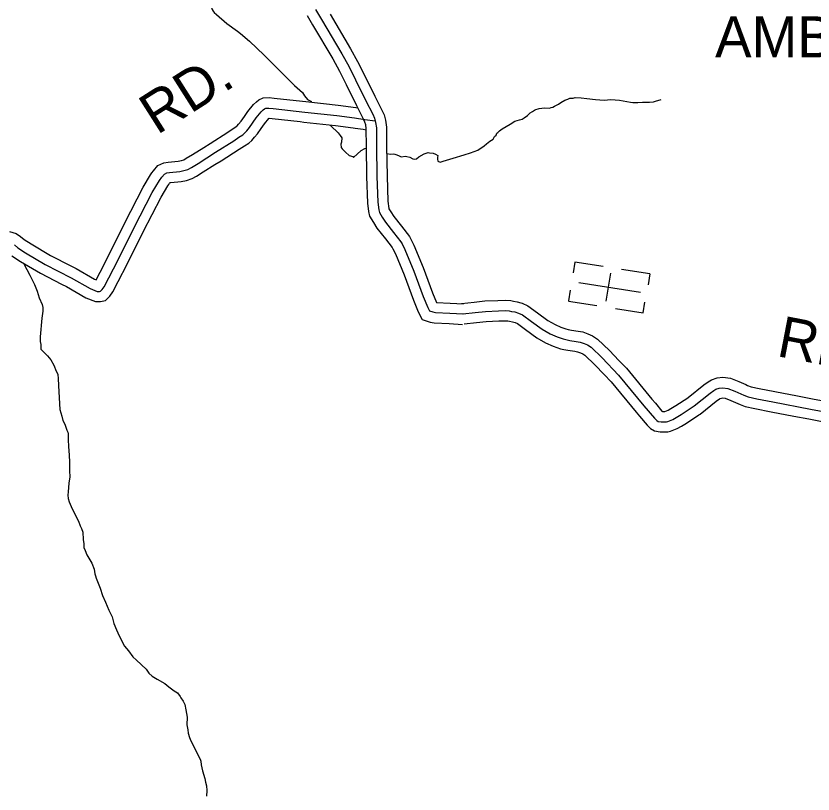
# Model space of a CAD drawing. Extents: x 1551132 to 1791609, y 378168 to 563823.
# Drawn here: x 1629673 to 1636863, y 428427 to 435445 of the extents above; entities that cross this region are included whole.
import ezdxf

# ---------------------------------------------------------------- set-up
doc = ezdxf.new("R2010")
doc.units = 0
for name, color, linetype in [('DESIGN - ROW - Right-of-Way and Easement Labels', 7, 'Continuous'), ('DESIGN - TRANSPORTATION - Text', 7, 'Continuous'), ('DESIGN - UTILITIES - Cable (Underground) with Text', 7, 'Continuous'), ('SURVEY - PROPERTY - Owners', 7, 'Continuous')]:
    doc.layers.add(name, color=color, linetype=linetype)

msp = doc.modelspace()

# ---------------------------------------------------------------- linework, layer by layer
at = {"layer": 'DESIGN - TRANSPORTATION - Text'}
for points in [[(1631371.443, 435634.795), (1631393.392, 435628.554), (1631397.376, 435626.512), (1631405.109, 435598.37), (1631428.658, 435550.027), (1631442.216, 435503.792), (1631452.066, 435487.658), (1631459.949, 435475.55), (1631481.79, 435457.283), (1631575.08, 435378.156), (1631670.469, 435309.029), (1631698.277, 435286.695), (1631779.658, 435217.71), (1631912.522, 435092.082), (1632186.032, 434816.683), (1632257.488, 434755.823), (1632277.205, 434725.556), (1632302.887, 434691.221), (1632340.178, 434672.062)], [(1633715.795, 434191.651), (1633772.186, 434210.368), (1633838.359, 434233.794), (1633896.683, 434273.311), (1633918.832, 434291.137), (1633949.048, 434316.896), (1633977.189, 434334.663), (1633989.406, 434358.58), (1634005.505, 434370.456), (1634011.647, 434386.423), (1634019.713, 434394.356), (1634035.83, 434408.232), (1634057.979, 434426.057), (1634132.311, 434467.433), (1634174.535, 434495.084), (1634214.617, 434506.726), (1634240.667, 434514.501), (1634256.766, 434526.368), (1634286.941, 434548.119), (1634311.148, 434571.936), (1634331.24, 434583.77), (1634351.322, 434593.595), (1634362.922, 434602.245), (1634383.422, 434607.32), (1634393.455, 434611.229), (1634441.454, 434614.796), (1634485.394, 434612.379), (1634501.444, 434618.237), (1634517.269, 434622.696), (1634531.527, 434629.979), (1634565.684, 434649.696), (1634587.817, 434665.514), (1634623.974, 434685.206), (1634652.041, 434694.964), (1634668.107, 434702.831), (1634698.098, 434704.548), (1634718.122, 434708.373), (1634772.054, 434705.865), (1634823.978, 434701.381), (1634901.843, 434692.639), (1634979.724, 434685.906), (1635039.731, 434691.365), (1635117.638, 434686.631), (1635217.394, 434667.672), (1635237.335, 434663.481), (1635281.317, 434665.081), (1635325.325, 434668.672), (1635387.273, 434668.097), (1635425.264, 434669.748), (1635441.305, 434675.606), (1635493.412, 434691.148)], [(1632506.241, 434460.49), (1632512.707, 434452.557), (1632580.156, 434391.739), (1632597.913, 434365.496), (1632613.73, 434345.296), (1632609.355, 434307.261), (1632603.155, 434287.286), (1632606.863, 434257.185), (1632614.771, 434247.076), (1632644.496, 434216.709), (1632680.228, 434186.275), (1632712.144, 434175.925), (1632717.694, 434169.125)], [(1632717.694, 434169.125), (1632788.084, 434232.593), (1632820.325, 434248.193), (1632834.4, 434251.51)], [(1633016.895, 434205.559), (1633021.995, 434203.351), (1633047.944, 434196.984), (1633078.027, 434200.584), (1633092.018, 434198.392), (1633107.951, 434192.159), (1633129.851, 434181.842), (1633147.767, 434173.575), (1633187.883, 434179.05), (1633199.866, 434176.883), (1633225.815, 434170.517), (1633253.665, 434156.099), (1633269.239, 434152.883), (1633285.697, 434155.666), (1633305.98, 434175.442), (1633356.371, 434200.826), (1633390.561, 434212.393), (1633404.544, 434210.193), (1633436.527, 434205.751), (1633456.443, 434197.459), (1633478.343, 434187.142), (1633476.076, 434167.117), (1633475.901, 434153.091), (1633479.668, 434134.991), (1633499.559, 434124.699), (1633527.75, 434136.341), (1633618.173, 434161.183), (1633716.687, 434191.926)], [(1629745.771, 433209.206), (1629799.703, 433107.82), (1629840.911, 433023.218), (1629864.335, 432962.85), (1629883.76, 432902.523), (1629909.192, 432842.138), (1629914.925, 432814.021), (1629914.609, 432781.953), (1629907.976, 432717.893), (1629892.351, 432551.714), (1629891.917, 432507.621), (1629897.667, 432481.512), (1629899.259, 432439.411), (1629915.092, 432421.21), (1629956.708, 432378.693), (1629988.39, 432344.292), (1630013.94, 432295.924), (1630037.406, 432239.564), (1630051.155, 432213.372), (1630052.747, 432171.271), (1630061.622, 432054.934), (1630070.063, 431894.522), (1630087.504, 431836.22), (1630095.121, 431796.052), (1630114.82, 431763.785), (1630132.278, 431707.492), (1630142.128, 431691.35), (1630143.978, 431675.299), (1630145.453, 431621.173), (1630148.861, 431561.013), (1630154.127, 431484.803), (1630155.502, 431420.659), (1630156.736, 431342.482), (1630160.211, 431288.331), (1630151.661, 431232.304)], [(1630151.661, 431232.304), (1630144.877, 431152.211), (1630140.578, 431122.193), (1630144.286, 431092.092), (1630154.002, 431061.933), (1630179.41, 430999.54), (1630238.367, 430888.704), (1630251.966, 430846.478), (1630265.741, 430822.285), (1630275.433, 430790.118), (1630280.774, 430721.916), (1630286.407, 430683.782), (1630284.232, 430665.765), (1630286.074, 430649.714), (1630297.824, 430623.539), (1630311.465, 430585.321), (1630358.747, 430508.669), (1630378.255, 430456.368), (1630383.846, 430414.216), (1630389.655, 430394.116), (1630397.463, 430373.999), (1630432.604, 430283.446), (1630453.97, 430217.086), (1630481.402, 430156.676), (1630510.735, 430086.233), (1630540.168, 430025.798), (1630557.592, 429965.496), (1630581.058, 429909.137), (1630604.524, 429852.777), (1630651.673, 429762.108), (1630687.281, 429719.648), (1630728.78, 429665.105), (1630760.504, 429634.713), (1630847.777, 429553.644), (1630873.434, 429517.31), (1630901.2, 429490.968), (1630946.949, 429462.433), (1631016.623, 429423.633), (1631052.355, 429393.198), (1631100.029, 429356.631), (1631129.87, 429338.289), (1631153.569, 429305.979), (1631161.461, 429293.871), (1631181.194, 429265.603), (1631196.91, 429235.386), (1631206.426, 429185.176), (1631217.793, 429118.925), (1631215.126, 429050.815), (1631222.684, 429004.638), (1631226.393, 428974.538), (1631240.026, 428936.32), (1631251.759, 428908.136), (1631265.492, 428879.943), (1631296.891, 428815.483), (1631334.207, 428742.948), (1631342.015, 428722.823), (1631343.706, 428690.738), (1631357.181, 428636.487), (1631378.514, 428566.127), (1631384.205, 428534.001), (1631391.872, 428499.85), (1631395.488, 428459.732), (1631390.972, 428407.664)]]:
    msp.add_lwpolyline(points, dxfattribs=at)
at = {"layer": 'DESIGN - UTILITIES - Cable (Underground) with Text'}
for p, q in [((1634715.857, 433224.98), (1634700.326, 433126.466)), ((1634969.378, 433184.684), (1634715.766, 433224.98)), ((1635390.628, 433117.983), (1635135.7, 433158.287)), ((1635035.119, 433123.703), (1634995.473, 432873.208)), ((1635390.587, 433117.849), (1635375.147, 433019.643)), ((1634671.861, 432972.027), (1634656.33, 432874.128)), ((1634656.155, 432873.603), (1634913.725, 432832.774)), ((1635331.017, 432766.914), (1635346.366, 432863.887)), ((1635082.73, 432806.11), (1635330.926, 432766.739))]:
    msp.add_line(p, q, dxfattribs=at)
msp.add_lwpolyline([(1634751.059, 433041.685), (1635307.124, 432953.693)], dxfattribs=at)
at = {"layer": 'SURVEY - PROPERTY - Owners'}
for points in [[(1632375.803, 435504.059), (1632429.235, 435413.407), (1632613.289, 435103.174), (1632674.57, 434990.404), (1632735.794, 434869.618), (1632830.575, 434680.396), (1632891.782, 434557.601), (1632907.548, 434521.384), (1632917.298, 434485.216), (1632924.939, 434435.023), (1632925.722, 434270.594), (1632929.722, 433997.862), (1632938.013, 433765.197), (1632947.513, 433694.937), (1632951.363, 433672.853), (1632977.096, 433630.544), (1633006.812, 433584.193), (1633080.26, 433491.382), (1633145.758, 433406.655), (1633155.642, 433388.529), (1633181.316, 433338.203), (1633262.031, 433143.073), (1633346.512, 432915.825), (1633387.844, 432815.248), (1633403.652, 432785.047), (1633433.635, 432774.788), (1633457.642, 432770.588), (1633585.831, 432763.572), (1633706.012, 432756.621)], [(1632299.038, 435448.599), (1632348.078, 435365.406), (1632531.29, 435056.589), (1632591.081, 434946.57), (1632651.587, 434827.183), (1632746.227, 434638.245), (1632806.309, 434517.725), (1632818.317, 434490.125), (1632824.883, 434465.791), (1632830.683, 434427.665), (1632831.433, 434269.677), (1632835.458, 433995.495), (1632843.949, 433757.18), (1632854.315, 433680.52), (1632861.54, 433639.086), (1632897.114, 433580.593), (1632929.964, 433529.35), (1633005.995, 433433.289), (1633066.569, 433354.92), (1633072.243, 433344.52), (1633095.618, 433298.694), (1633174.249, 433108.614), (1633258.689, 432881.466), (1633302.288, 432775.38), (1633337.554, 432708.003), (1633410.102, 432683.178), (1633446.901, 432676.744), (1633580.531, 432669.427), (1633700.57, 432662.486)], [(1632507.308, 435459.583), (1632692.17, 435147.992), (1632754.885, 435032.58), (1632816.8, 434910.436), (1632911.715, 434720.947), (1632974.013, 434595.969), (1632993.388, 434551.46), (1633006.204, 434503.908), (1633015.612, 434442.107), (1633016.429, 434271.477), (1633020.403, 434000.145), (1633028.503, 433772.906), (1633037.169, 433708.813), (1633037.778, 433705.338), (1633054.036, 433678.604), (1633080.735, 433636.952), (1633151.708, 433547.275), (1633221.94, 433456.423), (1633235.873, 433430.864), (1633263.756, 433376.212), (1633346.479, 433176.224), (1633430.993, 432948.885), (1633467.101, 432861.024), (1633467.976, 432860.866), (1633590.931, 432854.141), (1633711.245, 432847.182)], [(1629614.958, 433501.789), (1629673.923, 433481.621), (1629714.297, 433456.321), (1629746.505, 433429.72), (1629810.212, 433388.961), (1629983.957, 433285.575), (1630167.695, 433191.064), (1630216.885, 433165.772), (1630381.631, 433070.986), (1630396.256, 433065.536), (1630431.53, 433133.738), (1630511.662, 433288.65), (1630655.392, 433578.866), (1630656.017, 433580.141), (1630820.388, 433899.058), (1630887.745, 434011.844), (1630900.528, 434030.262), (1630913.519, 434048.945), (1630954.643, 434096.238), (1631006.042, 434119.497), (1631045.55, 434125.931), (1631136.923, 434136.339), (1631166.239, 434141.323), (1631187.08, 434148.098), (1631209.679, 434160.715), (1631265.786, 434194.808), (1631368.076, 434259.776), (1631424.149, 434295.394), (1631585.837, 434397.513), (1631632.428, 434429.431), (1631665.019, 434449.69), (1631669.744, 434453.523), (1631681.668, 434467.89), (1631703.801, 434495.149), (1631733.667, 434536.9), (1631766.316, 434582.551), (1631815.865, 434644.678), (1631842.79, 434671.212), (1631865.481, 434688.013), (1631902.088, 434706.746), (1631957.337, 434708.705), (1632002.144, 434704.53), (1632258.397, 434675.613), (1632289.354, 434672.121)], [(1632289.296, 434672.129), (1632578.556, 434639.695), (1632739.902, 434618.228), (1632757.16, 434615.845), (1632758.86, 434615.611)], [(1629659.015, 433379.685), (1629690.881, 433353.368), (1629760.688, 433308.709), (1629938.242, 433203.056), (1630171.786, 433082.928), (1630341.382, 432985.359), (1630407.331, 432960.783), (1630427.364, 432960.633), (1630437.397, 432962.558), (1630451.53, 432976.484), (1630469.754, 433002.409), (1630595.793, 433246.057), (1630740.215, 433537.69), (1630902.853, 433853.24), (1630967.035, 433960.718), (1630988.026, 433990.936), (1631012.275, 434018.82), (1631033.525, 434028.437), (1631058.466, 434032.495), (1631150.172, 434042.945), (1631188.838, 434049.521), (1631224.987, 434061.271), (1631257.153, 434079.221), (1631315.552, 434114.706), (1631474.598, 434215.733), (1631637.669, 434318.728), (1631683.985, 434350.454), (1631719.809, 434372.729), (1631736.35, 434386.138), (1631754.542, 434408.055), (1631778.808, 434437.939), (1631841.573, 434525.683), (1631886.072, 434581.477), (1631904.238, 434599.385), (1631915.338, 434607.602), (1631926.379, 434613.252), (1631954.62, 434614.252), (1631992.486, 434610.727), (1632278.788, 434578.418), (1632567.089, 434546.093), (1632727.236, 434524.792), (1632819.308, 434512.05), (1632913.948, 434497.65)], [(1629637.399, 433279.899), (1629713.047, 433231.507), (1629894.268, 433123.671), (1630083.08, 433026.543), (1630128.404, 433003.234), (1630302.666, 432902.982), (1630390.648, 432870.197), (1630435.647, 432869.856), (1630481.479, 432878.648), (1630521.028, 432917.615), (1630547.494, 432955.266), (1630595.843, 433048.736), (1630676.725, 433205.09), (1630821.246, 433496.914), (1630821.213, 433496.856), (1630982.184, 433809.164), (1631043.316, 433911.533), (1631052.458, 433924.709), (1631059.699, 433935.126), (1631065.441, 433941.726), (1631070.891, 433942.609), (1631162.922, 433953.101), (1631210.579, 433961.202), (1631261.453, 433977.744), (1631302.819, 434000.828), (1631363.426, 434037.654), (1631467.265, 434103.614), (1631523.13, 434139.098), (1631687.535, 434242.934), (1631733.584, 434274.477), (1631772.524, 434298.694), (1631800.424, 434321.311), (1631824.648, 434350.495), (1631850.964, 434382.905), (1631884.13, 434429.264), (1631913.963, 434470.974), (1631953.604, 434520.675), (1631955.987, 434523.025), (1631983.195, 434520.492), (1632237.664, 434491.774), (1632268.621, 434488.283)], [(1632268.68, 434488.274), (1632556.056, 434456.049), (1632715.052, 434434.906), (1632731.819, 434432.59), (1632806.267, 434422.281), (1632830.958, 434418.523)], [(1633692.004, 432850.291), (1633806.193, 432864.749), (1633902.165, 432874.266), (1634021.413, 432879.308), (1634090.136, 432881.367), (1634136.302, 432877.641), (1634160.559, 432872.541), (1634194.217, 432866.633), (1634226.508, 432857.249), (1634238.374, 432853.799), (1634289.556, 432831.174), (1634379.179, 432766.372), (1634472.285, 432698.379), (1634535.85, 432662.194), (1634589.232, 432637.369), (1634633.198, 432622.235), (1634652.981, 432618.077), (1634684.322, 432611.476), (1634743.129, 432603.051), (1634785.853, 432595.084), (1634832.36, 432579.059), (1634874.409, 432560.142), (1634919.833, 432531.091), (1635027.255, 432427.947), (1635112.545, 432337.353), (1635179.21, 432266.551), (1635410.321, 431989.711), (1635441.012, 431952.693), (1635500.244, 431881.208), (1635503.986, 431877.783), (1635514.252, 431877.799), (1635526.91, 431878.333), (1635557.801, 431889.866), (1635580.15, 431903.35), (1635624.766, 431929.968), (1635732.264, 432000.886), (1635736.03, 432003.369), (1635877.419, 432116.823), (1635917.718, 432146.082), (1635948.175, 432163.949), (1635996.958, 432179.716), (1636050.073, 432185.858), (1636117.313, 432176.674), (1636192.553, 432146.99), (1636255.993, 432119.923), (1636272.901, 432112.706), (1636305.367, 432100.972), (1636375.765, 432083.989), (1636519.287, 432056.963), (1636724.057, 432017.529), (1636858.587, 431991.62), (1637100.69, 431945.485)], [(1633703.845, 432756.746), (1633816.767, 432771.039), (1633908.815, 432780.172), (1634024.812, 432785.072), (1634087.744, 432786.956), (1634122.76, 432784.131), (1634142.71, 432779.939), (1634172.842, 432774.647), (1634206.025, 432765.005), (1634242.357, 432748.947), (1634323.747, 432690.087), (1634421.003, 432619.068), (1634492.576, 432578.334), (1634553.908, 432549.8), (1634608.057, 432531.166), (1634667.906, 432518.574), (1634727.796, 432509.991), (1634761.72, 432503.665), (1634797.586, 432491.307), (1634829.427, 432476.981), (1634861.218, 432456.648), (1634960.24, 432361.578), (1635108.628, 432203.958), (1635337.84, 431929.409), (1635431.737, 431816.106), (1635453.42, 431796.189), (1635466.253, 431787.78), (1635491.852, 431783.455), (1635516.327, 431783.514), (1635540.56, 431784.522), (1635552.343, 431787.172), (1635599, 431804.598), (1635628.658, 431822.49), (1635674.907, 431850.082), (1635791.604, 431927.068), (1635934.659, 432041.854), (1635969.391, 432067.08), (1635986.983, 432077.397), (1636017.065, 432087.122), (1636049.09, 432090.822), (1636093.289, 432084.788), (1636156.737, 432059.755), (1636238.36, 432024.929), (1636278.201, 432010.528), (1636355.974, 431991.761), (1636501.646, 431964.336), (1636840.846, 431899.009), (1637084.282, 431852.625)], [(1633715.236, 432666.752), (1633826.942, 432680.894), (1633915.215, 432689.653), (1634028.087, 432694.42), (1634085.444, 432696.137), (1634109.735, 432694.178), (1634125.535, 432690.853), (1634152.284, 432686.161), (1634174.892, 432679.586), (1634174.901, 432679.586), (1634196.95, 432669.844), (1634270.423, 432616.701), (1634371.671, 432542.775), (1634450.944, 432497.657), (1634519.926, 432465.564), (1634583.874, 432443.555), (1634614.898, 432437.03), (1634652.114, 432429.197), (1634713.046, 432420.472), (1634738.504, 432415.721), (1634764.137, 432406.888), (1634786.153, 432396.979), (1634804.836, 432385.037), (1634895.767, 432297.727), (1634977.856, 432210.541), (1635040.73, 432143.748), (1635268.108, 431871.399), (1635298.574, 431834.64), (1635365.83, 431753.471), (1635397.513, 431724.37), (1635432.421, 431701.503), (1635484.353, 431692.728), (1635518.318, 431692.811), (1635552.493, 431694.228), (1635578.284, 431700.028), (1635638.632, 431722.57), (1635675.323, 431744.704), (1635723.139, 431773.23), (1635834.103, 431846.44), (1635845.061, 431853.666), (1635989.724, 431969.735), (1636019.107, 431991.078), (1636024.315, 431994.136), (1636036.407, 431998.045), (1636048.148, 431999.403), (1636070.181, 431996.394), (1636122.288, 431975.836), (1636183.403, 431949.752), (1636205.128, 431940.485), (1636252.068, 431923.518), (1636336.933, 431903.042), (1636484.679, 431875.225), (1636689.074, 431835.857), (1636823.78, 431809.915), (1637068.499, 431763.289)]]:
    msp.add_lwpolyline(points, dxfattribs=at)

# ---------------------------------------------------------------- texts
at = {"layer": 'DESIGN - ROW - Right-of-Way and Easement Labels'}
for s, height, rotation, p in [('AMBER LYNN', 369.9913, 0.0000333, (1635979.185, 435070.975)), ('RD.', 369.9968, 32.4234306, (1630945.619, 434366.987)), ('RD.', 369.9919, 349.0989694, (1636525.762, 432378.546))]:
    msp.add_text(s, height=height, rotation=rotation, dxfattribs=at).set_placement(p)

doc.saveas('drawing.dxf')
